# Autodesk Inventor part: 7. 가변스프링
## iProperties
Created: 2015-01
Part Number: 7. 가변스프링
Document SubType Name: Modeling
Designer: elite
Density: 7.87 g/cm^3
Material: 탄소강
Mass: 79.8318 g
Surface Area: 103.431 cm^2
Volume: 10.1438 cm^3
Author: elite
